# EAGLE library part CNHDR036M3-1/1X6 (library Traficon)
PIN HEADER
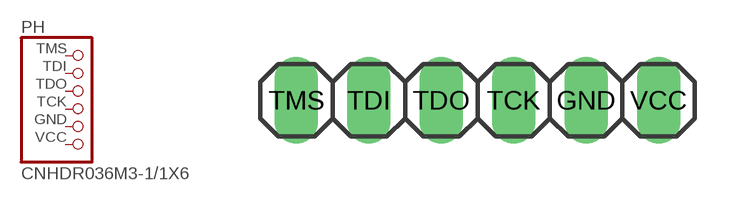
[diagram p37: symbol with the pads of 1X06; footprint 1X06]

Designator prefix PH

## CNHDR036M3-1/1X6  [1X06]
GND  5  pas
TCK  4  pas
TDI  2  pas
TDO  3  pas
TMS  1  pas
VCC  6  pas

## Footprint 1X06 (pad centres in mm)
PIN HEADER
drill 1.016 long: GND 3.81,0; TCK 1.27,0; TDI -3.81,0; TDO -1.27,0; TMS -6.35,0; VCC 6.35,0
